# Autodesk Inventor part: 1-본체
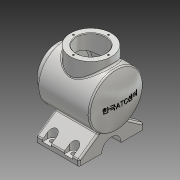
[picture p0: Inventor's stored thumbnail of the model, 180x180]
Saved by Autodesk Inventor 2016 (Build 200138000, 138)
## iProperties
Created: 2017-04
Part Number: 1-본체
Material: 알루미늄 6061
Document SubType Name: Modeling
Designer: H
Density: 2.7 g/cm^3
Appearance: 알루미늄 - 평지
Mass: 1664.76 g
Surface Area: 1067.86 cm^2
Volume: 616.577 cm^3
Author: H
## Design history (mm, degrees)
sketch "스케치2"
  geometry: L1 (47.998, 132)-(-48.338, 132); L2 (-60.002, 82)-(47.998, 82); L3 (47.998, 82)-(47.998, 132); A1 r 113 centre (52.998, 82) between (-48.338, 132) and (-60.002, 82); 3 further points
  constraints: 6 end point, 2 midpoint, 2 point on circle, 1 centre point, 1 horizontal, 1 parallel, 1 point on line, 1 vertical
  dimensions: "d2" = 108 distance from line of L2.start L3; "d3" = 82 vertical distance of L2.start point (0, 0); "d4" = 100 diameter of L1 L2; "d5" = 113 radius of A1; "d97" = 0.17 horizontal distance of point (0, 0) point (-0.17, 132)
revolve "회전1" sketch "스케치2" stored, may be unused: angle "d6" = 90 deg
node "작업 평면1"
sketch "스케치4"
  geometry: L1 (-47.998, 50)-(-47.998, -50) reference; C1 r 38 at (2.002, 0); 1 further point
  constraints: 1 centre point, 1 horizontal alignment
  dimensions: "d74" = 50 distance from line of L1 C1.centre; "d75" = 76 diameter of C1
extrude "돌출1" join sketch "스케치4" stored distance "d9" = 10; taper "d10" = 0 deg
sketch "스케치5"
  geometry: C1 r 38 at (0, 0); C2 r 50 at (0, 0) reference; 1 further point
  constraints: 1 centre point, 1 concentric
  dimensions: "d11" = 76 diameter of C1
extrude "돌출2" join sketch "스케치5" distance "d12" = 12; taper "d13" = 0 deg
feature "쉘1" dims "d14" = 10, "d15" = 11
sketch "스케치6"
  geometry: L1 (60, 10)-(-60, 10); L2 (-60, 10)-(-60, 0); L3 (-60, 0)-(60, 0); L4 (60, 0)-(60, 10); L5 (60, 10)-(14.299, 42); L6 (14.299, 42)-(-14.299, 42); L7 (-14.299, 42)-(-60, 10); 4 further points
  constraints: 14 end point, 2 horizontal, 2 midpoint, 2 parallel, 1 coincident, 1 equal length, 1 perpendicular, 1 vertical alignment, 1 other
  dimensions: "d16" = 120 distance of L2.end L3.end; "d17" = 10 distance of L1.end L2.end; "d18" = 55 deg angle of L4 L5
extrude "돌출3" join sketch "스케치6" stored distance "d19" = 80; taper "d20" = 0 deg
sketch "스케치7"
  geometry: C1 r 18 at (0, 0); 1 further point
  constraints: 1 centre point, 1 coincident
  dimensions: "d21" = 18 radius of C1
extrude "돌출4" cut sketch "스케치7" stored distance "d22" = 80; taper "d23" = 0 deg
node "작업 평면2"
sketch "스케치10"
  geometry: L1 (20, -50)-(20, -70); L2 (12, -50)-(12, -70); L3 (28, -70)-(28, -50); L4 (-40, -60)-(40, -60) reference; L5 (40, -21.584)-(40, -60) reference; A1 r 8 centre (20, -50) between (28, -50) and (12, -50); A2 r 8 centre (20, -70) between (12, -70) and (28, -70); 2 further points
  constraints: 8 end point, 4 point on circle, 4 tangent, 2 centre point, 1 midpoint, 1 parallel, 1 point on line, 1 vertical
  dimensions: "d27" = 20 distance between parallel lines of L5 L1; "d28" = 10 distance from line of L4 L1.start; "d29" = 16 distance between parallel lines of L2 L3
extrude "돌출5" cut sketch "스케치10" distance "d30" = 24; taper "d31" = 0 deg
hole "구멍1" diameter "d34" = 8; stored, may be unused: countersink angle "d38" = 90 deg, drill point angle "d40" = 118 deg; dims "d32" = 10, "d33" = 10, "d35" = 6, "d36" = 4, "d37" = 2, "d39" = 8
sketch "스케치11"
  geometry: L1 (0, 0)-(32.5, 0); C1 r 38 at (0, 0) reference; 2 further points
  constraints: 2 coincident, 2 end point, 1 horizontal
  dimensions: "d41" = 32.5 distance of L1.start L1.end
hole "구멍2" sketch "스케치11" at (32.5, 0) diameter "d42" = 3.242; stored, may be unused: countersink angle "d46" = 90 deg, drill point angle "d48" = 118 deg; dims "d43" = 8, "d44" = 4, "d45" = 2, "d47" = 10
sketch "스케치14"
  geometry: L1 (0, 0)-(32.5, 0); C1 r 38 at (0, 0) reference; 2 further points
  constraints: 2 coincident, 2 end point, 1 horizontal
  dimensions: "d84" = 32.5 distance of L1.start L1.end
hole "구멍5" sketch "스케치14" at (32.5, 0) diameter "d85" = 3.242; stored, may be unused: countersink angle "d89" = 90 deg, drill point angle "d91" = 118 deg; dims "d86" = 8, "d87" = 4, "d88" = 2, "d90" = 10
node "작업 평면3"
chamfer "모따기1" distance "d66" = 1; stored, may be unused: second distance "d67" = 2, angle "d68" = 45 deg
fillet "모깎기1" dims "d69" = 3
fillet "모깎기2" dims "d70" = 3
fillet "모깎기3" dims "d71" = 3
fillet "모깎기4" dims "d72" = 3
sketch "스케치13"
  geometry: L1 (18, -82)-(60, -82) reference; 2 further points
  constraints: 1 vertical alignment, 1 other
  dimensions: "d63" = 82 distance from line of L1 point (0, 0)
feature "엠보싱1" sketch "스케치13" dims "d2" = 108, "d3" = 82, "d4" = 100, "d5" = 113, "d64" = 0.5, "d65" = 0, "d97" = 0.17
fillet "모깎기5" dims "d73" = 3
fillet "모깎기6" dims "d95" = 3
node "솔리드1"
mirror "대칭3"
mirror "대칭4"
pattern_circular "원형 패턴1" dims angle "d50" = 360 deg
pattern_circular "원형 패턴3" dims angle "d93" = 360 deg
other parameters: "d7" = 147
